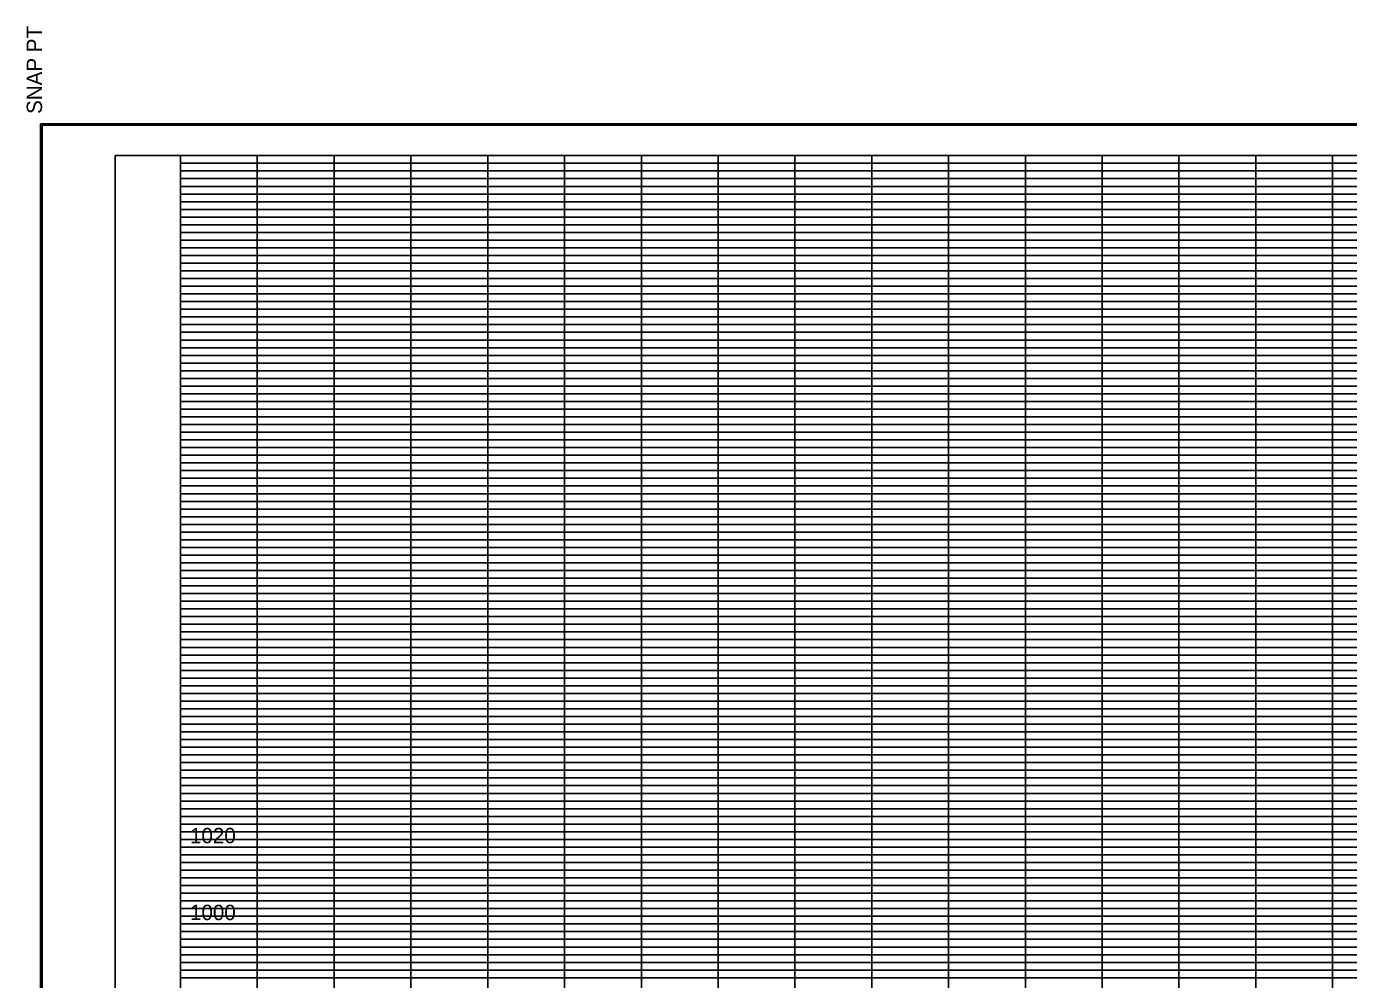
# Model space of a CAD drawing. Extents: x 2313580 to 2322968, y 282099 to 303247.
# Drawn here: x 2316050 to 2316394.2, y 287793.2 to 288041.3 of the extents above; entities that cross this region are included whole.
import ezdxf

# ---------------------------------------------------------------- set-up
doc = ezdxf.new("R2010")
doc.units = 0
for name, color, linetype in [('DESIGN - SHEET - Corner Text', 7, 'Continuous'), ('DESIGN - SHEET - Light Grid', 7, 'Continuous'), ('DESIGN - SHEET - Linework', 7, 'Continuous'), ('DESIGN - SHEET - Plot Shape', 7, 'Continuous'), ('DESIGN - TYPICAL - Text', 7, 'Continuous')]:
    doc.layers.add(name, color=color, linetype=linetype)

msp = doc.modelspace()

# ---------------------------------------------------------------- linework, layer by layer
at = {"layer": 'DESIGN - SHEET - Light Grid'}
for p, q in [((2316090.08, 288005.67), (2316250.08, 288005.67)), ((2316250.08, 288005.67), (2316410.08, 288005.67)), ((2316090.08, 288003.67), (2316250.08, 288003.67)), ((2316090.08, 288001.67), (2316250.08, 288001.67)), ((2316250.08, 288003.67), (2316410.08, 288003.67)), ((2316250.08, 288001.67), (2316410.08, 288001.67)), ((2316090.08, 287999.67), (2316250.08, 287999.67)), ((2316090.08, 287997.67), (2316250.08, 287997.67)), ((2316250.08, 287999.67), (2316410.08, 287999.67)), ((2316250.08, 287997.67), (2316410.08, 287997.67)), ((2316090.08, 287995.67), (2316250.08, 287995.67)), ((2316250.08, 287995.67), (2316410.08, 287995.67)), ((2316090.08, 287993.67), (2316250.08, 287993.67)), ((2316090.08, 287991.67), (2316250.08, 287991.67)), ((2316250.08, 287993.67), (2316410.08, 287993.67)), ((2316250.08, 287991.67), (2316410.08, 287991.67)), ((2316090.08, 287989.67), (2316250.08, 287989.67)), ((2316250.08, 287989.67), (2316410.08, 287989.67)), ((2316090.08, 287985.67), (2316250.08, 287985.67)), ((2316090.08, 287983.67), (2316250.08, 287983.67)), ((2316250.08, 287985.67), (2316410.08, 287985.67)), ((2316250.08, 287983.67), (2316410.08, 287983.67)), ((2316090.08, 287981.67), (2316250.08, 287981.67)), ((2316250.08, 287981.67), (2316410.08, 287981.67)), ((2316090.08, 287979.67), (2316250.08, 287979.67)), ((2316090.08, 287977.67), (2316250.08, 287977.67)), ((2316250.08, 287979.67), (2316410.08, 287979.67)), ((2316250.08, 287977.67), (2316410.08, 287977.67)), ((2316090.08, 287975.67), (2316250.08, 287975.67)), ((2316090.08, 287973.67), (2316250.08, 287973.67)), ((2316250.08, 287975.67), (2316410.08, 287975.67)), ((2316250.08, 287973.67), (2316410.08, 287973.67)), ((2316090.08, 287971.67), (2316250.08, 287971.67)), ((2316250.08, 287971.67), (2316410.08, 287971.67)), ((2316090.08, 287969.67), (2316250.08, 287969.67)), ((2316250.08, 287969.67), (2316410.08, 287969.67)), ((2316090.08, 287965.67), (2316250.08, 287965.67)), ((2316090.08, 287963.67), (2316250.08, 287963.67)), ((2316250.08, 287965.67), (2316410.08, 287965.67)), ((2316250.08, 287963.67), (2316410.08, 287963.67)), ((2316090.08, 287961.67), (2316250.08, 287961.67)), ((2316090.08, 287959.67), (2316250.08, 287959.67)), ((2316250.08, 287961.67), (2316410.08, 287961.67)), ((2316250.08, 287959.67), (2316410.08, 287959.67)), ((2316090.08, 287957.67), (2316250.08, 287957.67)), ((2316250.08, 287957.67), (2316410.08, 287957.67)), ((2316090.08, 287955.67), (2316250.08, 287955.67)), ((2316090.08, 287953.67), (2316250.08, 287953.67)), ((2316250.08, 287955.67), (2316410.08, 287955.67)), ((2316250.08, 287953.67), (2316410.08, 287953.67)), ((2316090.08, 287951.67), (2316250.08, 287951.67)), ((2316090.08, 287949.67), (2316250.08, 287949.67)), ((2316250.08, 287951.67), (2316410.08, 287951.67)), ((2316250.08, 287949.67), (2316410.08, 287949.67)), ((2316090.08, 287945.67), (2316250.08, 287945.67)), ((2316250.08, 287945.67), (2316410.08, 287945.67)), ((2316090.08, 287943.67), (2316250.08, 287943.67)), ((2316250.08, 287943.67), (2316410.08, 287943.67)), ((2316090.08, 287941.67), (2316250.08, 287941.67)), ((2316090.08, 287939.67), (2316250.08, 287939.67)), ((2316250.08, 287941.67), (2316410.08, 287941.67)), ((2316250.08, 287939.67), (2316410.08, 287939.67)), ((2316090.08, 287937.67), (2316250.08, 287937.67)), ((2316090.08, 287935.67), (2316250.08, 287935.67)), ((2316250.08, 287937.67), (2316410.08, 287937.67)), ((2316250.08, 287935.67), (2316410.08, 287935.67)), ((2316090.08, 287933.67), (2316250.08, 287933.67)), ((2316250.08, 287933.67), (2316410.08, 287933.67)), ((2316090.08, 287931.67), (2316250.08, 287931.67)), ((2316090.08, 287929.67), (2316250.08, 287929.67)), ((2316250.08, 287931.67), (2316410.08, 287931.67)), ((2316250.08, 287929.67), (2316410.08, 287929.67)), ((2316090.08, 287925.67), (2316250.08, 287925.67)), ((2316250.08, 287925.67), (2316410.08, 287925.67)), ((2316090.08, 287923.67), (2316250.08, 287923.67)), ((2316090.08, 287921.67), (2316250.08, 287921.67)), ((2316250.08, 287923.67), (2316410.08, 287923.67)), ((2316250.08, 287921.67), (2316410.08, 287921.67)), ((2316090.08, 287919.67), (2316250.08, 287919.67)), ((2316250.08, 287919.67), (2316410.08, 287919.67)), ((2316090.08, 287917.67), (2316250.08, 287917.67)), ((2316090.08, 287915.67), (2316250.08, 287915.67)), ((2316250.08, 287917.67), (2316410.08, 287917.67)), ((2316250.08, 287915.67), (2316410.08, 287915.67)), ((2316090.08, 287913.67), (2316250.08, 287913.67)), ((2316090.08, 287911.67), (2316250.08, 287911.67)), ((2316250.08, 287913.67), (2316410.08, 287913.67)), ((2316250.08, 287911.67), (2316410.08, 287911.67)), ((2316090.08, 287909.67), (2316250.08, 287909.67)), ((2316250.08, 287909.67), (2316410.08, 287909.67)), ((2316090.08, 287905.67), (2316250.08, 287905.67)), ((2316250.08, 287905.67), (2316410.08, 287905.67)), ((2316090.08, 287903.67), (2316250.08, 287903.67)), ((2316090.08, 287901.67), (2316250.08, 287901.67)), ((2316250.08, 287903.67), (2316410.08, 287903.67)), ((2316250.08, 287901.67), (2316410.08, 287901.67)), ((2316090.08, 287899.67), (2316250.08, 287899.67)), ((2316090.08, 287897.67), (2316250.08, 287897.67)), ((2316250.08, 287899.67), (2316410.08, 287899.67)), ((2316250.08, 287897.67), (2316410.08, 287897.67)), ((2316090.08, 287895.67), (2316250.08, 287895.67)), ((2316250.08, 287895.67), (2316410.08, 287895.67)), ((2316090.08, 287893.67), (2316250.08, 287893.67)), ((2316090.08, 287891.67), (2316250.08, 287891.67)), ((2316250.08, 287893.67), (2316410.08, 287893.67)), ((2316250.08, 287891.67), (2316410.08, 287891.67)), ((2316090.08, 287889.67), (2316250.08, 287889.67)), ((2316250.08, 287889.67), (2316410.08, 287889.67)), ((2316090.08, 287885.67), (2316250.08, 287885.67)), ((2316090.08, 287883.67), (2316250.08, 287883.67)), ((2316250.08, 287885.67), (2316410.08, 287885.67)), ((2316250.08, 287883.67), (2316410.08, 287883.67)), ((2316090.08, 287881.67), (2316250.08, 287881.67)), ((2316250.08, 287881.67), (2316410.08, 287881.67)), ((2316090.08, 287879.67), (2316250.08, 287879.67)), ((2316090.08, 287877.67), (2316250.08, 287877.67)), ((2316250.08, 287879.67), (2316410.08, 287879.67)), ((2316250.08, 287877.67), (2316410.08, 287877.67)), ((2316090.08, 287875.67), (2316250.08, 287875.67)), ((2316090.08, 287873.67), (2316250.08, 287873.67)), ((2316250.08, 287875.67), (2316410.08, 287875.67)), ((2316250.08, 287873.67), (2316410.08, 287873.67)), ((2316090.08, 287871.67), (2316250.08, 287871.67)), ((2316250.08, 287871.67), (2316410.08, 287871.67)), ((2316090.08, 287869.67), (2316250.08, 287869.67)), ((2316250.08, 287869.67), (2316410.08, 287869.67)), ((2316090.08, 287865.67), (2316250.08, 287865.67)), ((2316090.08, 287863.67), (2316250.08, 287863.67)), ((2316250.08, 287865.67), (2316410.08, 287865.67)), ((2316250.08, 287863.67), (2316410.08, 287863.67)), ((2316090.08, 287861.67), (2316250.08, 287861.67)), ((2316090.08, 287859.67), (2316250.08, 287859.67)), ((2316250.08, 287861.67), (2316410.08, 287861.67)), ((2316250.08, 287859.67), (2316410.08, 287859.67)), ((2316090.08, 287857.67), (2316250.08, 287857.67)), ((2316250.08, 287857.67), (2316410.08, 287857.67)), ((2316090.08, 287855.67), (2316250.08, 287855.67)), ((2316090.08, 287853.67), (2316250.08, 287853.67)), ((2316250.08, 287855.67), (2316410.08, 287855.67)), ((2316250.08, 287853.67), (2316410.08, 287853.67)), ((2316090.08, 287851.67), (2316250.08, 287851.67)), ((2316090.08, 287849.67), (2316250.08, 287849.67)), ((2316250.08, 287851.67), (2316410.08, 287851.67)), ((2316250.08, 287849.67), (2316410.08, 287849.67)), ((2316090.08, 287845.67), (2316250.08, 287845.67)), ((2316090.08, 287843.67), (2316250.08, 287843.67)), ((2316250.08, 287845.67), (2316410.08, 287845.67)), ((2316250.08, 287843.67), (2316410.08, 287843.67)), ((2316090.08, 287841.67), (2316250.08, 287841.67)), ((2316090.08, 287839.67), (2316250.08, 287839.67)), ((2316250.08, 287841.67), (2316410.08, 287841.67)), ((2316250.08, 287839.67), (2316410.08, 287839.67)), ((2316090.08, 287837.67), (2316250.08, 287837.67)), ((2316090.08, 287835.67), (2316250.08, 287835.67)), ((2316250.08, 287837.67), (2316410.08, 287837.67)), ((2316250.08, 287835.67), (2316410.08, 287835.67)), ((2316090.08, 287833.67), (2316250.08, 287833.67)), ((2316250.08, 287833.67), (2316410.08, 287833.67)), ((2316090.08, 287831.67), (2316250.08, 287831.67)), ((2316090.08, 287829.67), (2316250.08, 287829.67)), ((2316250.08, 287831.67), (2316410.08, 287831.67)), ((2316250.08, 287829.67), (2316410.08, 287829.67)), ((2316090.08, 287825.67), (2316250.08, 287825.67)), ((2316250.08, 287825.67), (2316410.08, 287825.67)), ((2316090.08, 287823.67), (2316250.08, 287823.67)), ((2316250.08, 287823.67), (2316410.08, 287823.67)), ((2316090.08, 287821.67), (2316250.08, 287821.67)), ((2316090.08, 287819.67), (2316250.08, 287819.67)), ((2316250.08, 287821.67), (2316410.08, 287821.67)), ((2316250.08, 287819.67), (2316410.08, 287819.67)), ((2316090.08, 287817.67), (2316250.08, 287817.67)), ((2316090.08, 287815.67), (2316250.08, 287815.67)), ((2316250.08, 287817.67), (2316410.08, 287817.67)), ((2316250.08, 287815.67), (2316410.08, 287815.67)), ((2316090.08, 287813.67), (2316250.08, 287813.67)), ((2316090.08, 287811.67), (2316250.08, 287811.67)), ((2316250.08, 287813.67), (2316410.08, 287813.67)), ((2316250.08, 287811.67), (2316410.08, 287811.67)), ((2316090.08, 287809.67), (2316250.08, 287809.67)), ((2316250.08, 287809.67), (2316410.08, 287809.67)), ((2316090.08, 287805.67), (2316250.08, 287805.67)), ((2316250.08, 287805.67), (2316410.08, 287805.67)), ((2316090.08, 287803.67), (2316250.08, 287803.67)), ((2316090.08, 287801.67), (2316250.08, 287801.67)), ((2316250.08, 287803.67), (2316410.08, 287803.67)), ((2316250.08, 287801.67), (2316410.08, 287801.67)), ((2316090.08, 287799.67), (2316250.08, 287799.67)), ((2316090.08, 287797.67), (2316250.08, 287797.67)), ((2316250.08, 287799.67), (2316410.08, 287799.67)), ((2316250.08, 287797.67), (2316410.08, 287797.67)), ((2316090.08, 287795.67), (2316250.08, 287795.67)), ((2316250.08, 287795.67), (2316410.08, 287795.67)), ((2316090.08, 287793.67), (2316250.08, 287793.67)), ((2316250.08, 287793.67), (2316410.08, 287793.67))]:
    msp.add_line(p, q, dxfattribs=at)
at = {"layer": 'DESIGN - SHEET - Linework'}
for p, q in [((2316053.62, 287579.39), (2316053.62, 288015.95)), ((2316053.62, 288015.95), (2316734.42, 288015.95)), ((2316110.08, 287587.67), (2316110.08, 288007.67)), ((2316130.08, 287587.67), (2316130.08, 288007.67)), ((2316150.08, 287587.67), (2316150.08, 288007.67)), ((2316170.08, 287587.67), (2316170.08, 288007.67)), ((2316190.08, 287587.67), (2316190.08, 288007.67)), ((2316210.08, 287587.67), (2316210.08, 288007.67)), ((2316230.08, 287587.67), (2316230.08, 288007.67)), ((2316250.08, 287587.67), (2316250.08, 288007.67)), ((2316270.08, 287587.67), (2316270.08, 288007.67)), ((2316290.08, 287587.67), (2316290.08, 288007.67)), ((2316310.08, 287587.67), (2316310.08, 288007.67)), ((2316330.08, 287587.67), (2316330.08, 288007.67)), ((2316350.08, 287587.67), (2316350.08, 288007.67)), ((2316370.08, 287587.67), (2316370.08, 288007.67)), ((2316390.08, 287587.67), (2316390.08, 288007.67)), ((2316090.08, 287987.67), (2316650.08, 287987.67)), ((2316090.08, 287967.67), (2316730.08, 287967.67)), ((2316090.08, 287947.67), (2316730.08, 287947.67)), ((2316090.08, 287927.67), (2316730.08, 287927.67)), ((2316090.08, 287907.67), (2316730.08, 287907.67)), ((2316090.08, 287887.67), (2316730.08, 287887.67)), ((2316090.08, 287867.67), (2316730.08, 287867.67)), ((2316090.08, 287847.67), (2316730.08, 287847.67)), ((2316090.08, 287827.67), (2316730.08, 287827.67)), ((2316090.08, 287807.67), (2316730.08, 287807.67))]:
    msp.add_line(p, q, dxfattribs=at)
msp.add_lwpolyline([(2316090.08, 288007.67), (2316090.08, 287587.67), (2316730.08, 287587.67), (2316730.08, 288007.67), (2316090.08, 288007.67)], dxfattribs=at)
at = {"layer": 'DESIGN - SHEET - Plot Shape'}
for points in [[(2316054.02, 288015.55), (2316734.02, 288015.55), (2316734.02, 287579.79), (2316054.02, 287579.79)], [(2316073.08, 288007.67), (2316730.08, 288007.67), (2316730.08, 287582.67), (2316073.08, 287582.67)]]:
    msp.add_lwpolyline(points, close=True, dxfattribs=at)

# ---------------------------------------------------------------- texts
at = {"layer": 'DESIGN - SHEET - Corner Text'}
msp.add_text('  SNAP PT', height=4, rotation=90, dxfattribs=at).set_placement((2316054.02, 288015.55))
at = {"layer": 'DESIGN - TYPICAL - Text'}
for s, p in [('1020', (2316092.56, 287828.67)), ('1000', (2316092.56, 287808.67))]:
    msp.add_text(s, height=4, dxfattribs=at).set_placement(p)

doc.saveas('drawing.dxf')
